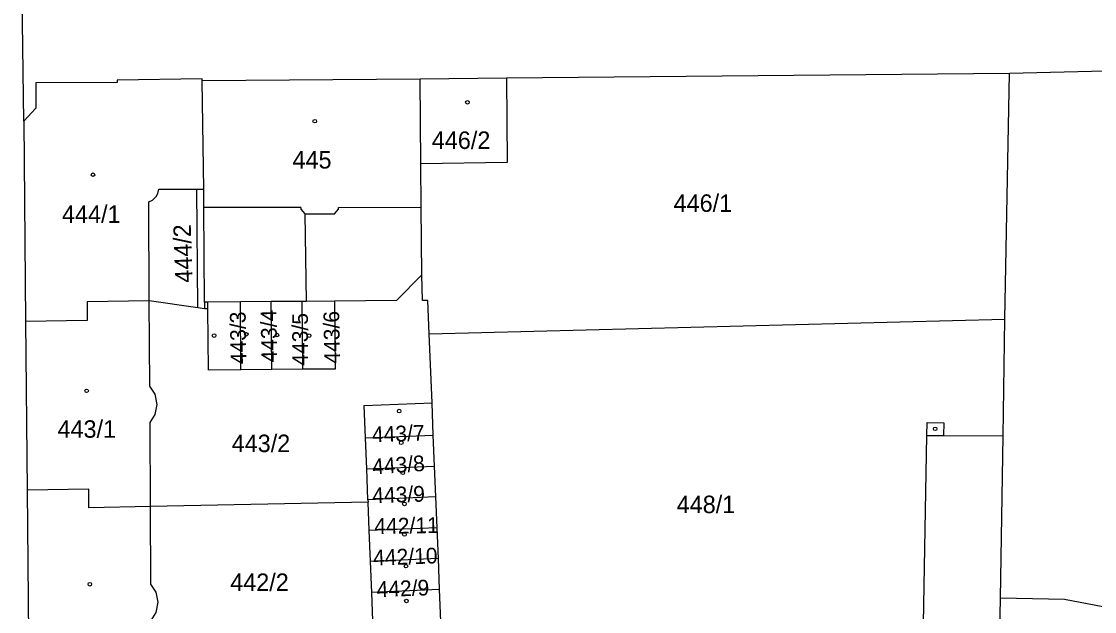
# Model space of a CAD drawing. Extents: x -733394 to -722299, y -1082822 to -1075049.
# Drawn here: x -728470.9 to -728366.6, y -1079471.2 to -1079413.8 of the extents above; entities that cross this region are included whole.
import ezdxf

# ---------------------------------------------------------------- set-up
doc = ezdxf.new("R2010")
doc.units = 0
for name, color, linetype in [('Hranice parcel', 7, 'Continuous'), ('Parcelní čísla', 7, 'Continuous'), ('Vnitřní kresba', 7, 'Continuous'), ('Značky budov', 7, 'Continuous')]:
    doc.layers.add(name, color=color, linetype=linetype)

msp = doc.modelspace()

# ---------------------------------------------------------------- linework, layer by layer
at = {"layer": 'Hranice parcel'}
for p, q in [((-728470.64, -1079423.53), (-728470.87, -1079404.92)), ((-728432.14, -1079419.44), (-728453.3, -1079419.62)), ((-728423.75, -1079419.36), (-728432.14, -1079419.44)), ((-728432.08, -1079427.67), (-728432.14, -1079419.44)), ((-728374.9, -1079418.91), (-728423.75, -1079419.36)), ((-728375.33, -1079442.75), (-728374.9, -1079418.91)), ((-728364, -1079418.64), (-728374.9, -1079418.91)), ((-728453.17, -1079430.12), (-728453.3, -1079419.62)), ((-728470.64, -1079423.53), (-728470.47, -1079442.98)), ((-728452.75, -1079441.1), (-728453.09, -1079441.1)), ((-728449.6, -1079441.07), (-728452.75, -1079441.1)), ((-728446.6, -1079441.05), (-728449.6, -1079441.07)), ((-728449.55, -1079447.67), (-728449.6, -1079441.07)), ((-728443.6, -1079441.03), (-728446.6, -1079441.05)), ((-728446.55, -1079447.65), (-728446.6, -1079441.05)), ((-728443.55, -1079447.63), (-728443.6, -1079441.03)), ((-728470.47, -1079442.98), (-728470.32, -1079459.36)), ((-728431.26, -1079444.2), (-728375.33, -1079442.75)), ((-728375.5, -1079454.1), (-728375.33, -1079442.75)), ((-728430.98, -1079450.89), (-728431.26, -1079444.2)), ((-728446.55, -1079447.65), (-728449.55, -1079447.67)), ((-728443.55, -1079447.63), (-728446.55, -1079447.65)), ((-728430.86, -1079454.03), (-728430.98, -1079450.89)), ((-728437.45, -1079454.3), (-728430.86, -1079454.03)), ((-728437.33, -1079457.3), (-728437.45, -1079454.3)), ((-728430.74, -1079457.03), (-728430.86, -1079454.03)), ((-728375.78, -1079469.87), (-728375.5, -1079454.1)), ((-728437.33, -1079457.3), (-728430.74, -1079457.03)), ((-728430.61, -1079460.03), (-728430.74, -1079457.03)), ((-728437.21, -1079460.3), (-728437.33, -1079457.3)), ((-728470.32, -1079459.36), (-728470.14, -1079480.06)), ((-728430.61, -1079460.03), (-728437.21, -1079460.3)), ((-728430.49, -1079463.03), (-728430.61, -1079460.03)), ((-728437.2, -1079460.52), (-728458.34, -1079460.95)), ((-728437.21, -1079460.3), (-728437.2, -1079460.52)), ((-728437.09, -1079463.29), (-728437.2, -1079460.52)), ((-728430.49, -1079463.03), (-728437.09, -1079463.29)), ((-728436.97, -1079466.29), (-728437.09, -1079463.29)), ((-728430.37, -1079466.02), (-728430.49, -1079463.03)), ((-728430.37, -1079466.02), (-728436.97, -1079466.29)), ((-728436.85, -1079469.29), (-728436.97, -1079466.29)), ((-728430.25, -1079469.02), (-728430.37, -1079466.02)), ((-728430.25, -1079469.02), (-728436.85, -1079469.29)), ((-728436.69, -1079472.97), (-728436.85, -1079469.29)), ((-728430.09, -1079472.87), (-728430.25, -1079469.02))]:
    msp.add_line(p, q, dxfattribs=at)
for points in [[(-728453.3, -1079419.62), (-728453.3, -1079419.43), (-728461.57, -1079419.54), (-728461.56, -1079419.76), (-728469.48, -1079419.81), (-728469.46, -1079422.28), (-728470.64, -1079423.53)], [(-728423.75, -1079419.36), (-728423.68, -1079427.56), (-728432.08, -1079427.67)], [(-728431.97, -1079438.44), (-728432.05, -1079431.89), (-728432.08, -1079427.67)], [(-728458.45, -1079440.99), (-728458.5, -1079431.37), (-728458.14, -1079431.19), (-728457.8, -1079430.86), (-728457.62, -1079430.54), (-728457.51, -1079430.15), (-728453.82, -1079430.13), (-728453.17, -1079430.12)], [(-728453.09, -1079441.1), (-728453.15, -1079431.92), (-728453.17, -1079430.12)], [(-728431.97, -1079438.44), (-728434.45, -1079440.96), (-728440.45, -1079441)], [(-728431.26, -1079444.2), (-728431.38, -1079440.94), (-728431.9, -1079440.94), (-728431.97, -1079438.44)], [(-728458.45, -1079440.99), (-728464.5, -1079441.08), (-728464.48, -1079442.89), (-728470.47, -1079442.98)], [(-728458.34, -1079460.95), (-728458.38, -1079452.81), (-728457.88, -1079452.02), (-728457.69, -1079451.04), (-728457.89, -1079450.05), (-728458.4, -1079449.27), (-728458.45, -1079440.99)], [(-728453.09, -1079441.1), (-728453.08, -1079441.75), (-728453.74, -1079441.66), (-728458.45, -1079440.99)], [(-728449.55, -1079447.67), (-728452.7, -1079447.7), (-728452.75, -1079441.75), (-728452.75, -1079441.1)], [(-728440.45, -1079441), (-728443.2, -1079441.03), (-728443.6, -1079441.03)], [(-728440.45, -1079441), (-728440.4, -1079447.6), (-728443.55, -1079447.63)], [(-728437.45, -1079454.3), (-728437.58, -1079451.15), (-728430.98, -1079450.89)], [(-728377.89, -1079535.66), (-728379.46, -1079537.61), (-728379.86, -1079537.3), (-728379.63, -1079537), (-728382.77, -1079533.71), (-728383.15, -1079533.73), (-728382.75, -1079526.18), (-728384.26, -1079526.14), (-728384.05, -1079523.07), (-728384.55, -1079523.06), (-728383.93, -1079506.08), (-728383.08, -1079506.09), (-728382.78, -1079498.3), (-728389.06, -1079498.02), (-728388.8, -1079490.97), (-728382.54, -1079491.22), (-728382.21, -1079479.61), (-728383.37, -1079479.6), (-728382.92, -1079454.06), (-728382.9, -1079452.81), (-728381.27, -1079452.84), (-728381.29, -1079454.07), (-728375.5, -1079454.1)], [(-728458.34, -1079460.95), (-728464.32, -1079461.07), (-728464.34, -1079459.28), (-728470.32, -1079459.36)], [(-728458.24, -1079479.88), (-728458.24, -1079479.17), (-728458.28, -1079472.03), (-728457.78, -1079471.24), (-728457.59, -1079470.26), (-728457.79, -1079469.27), (-728458.3, -1079468.49), (-728458.34, -1079460.95)], [(-728377.89, -1079535.66), (-728377.44, -1079523.13), (-728376.84, -1079506.33), (-728376.06, -1079484.54), (-728375.78, -1079469.87)], [(-728363.77, -1079471.1), (-728369.54, -1079469.97), (-728375.78, -1079469.87)]]:
    msp.add_lwpolyline(points, dxfattribs=at)
at = {"layer": 'Vnitřní kresba'}
for p, q in [((-728453.74, -1079441.66), (-728453.82, -1079430.13)), ((-728443.72, -1079431.91), (-728453.15, -1079431.92)), ((-728443.72, -1079431.91), (-728443.72, -1079432.08)), ((-728440.45, -1079432.53), (-728440.07, -1079432.07)), ((-728440.07, -1079431.9), (-728432.05, -1079431.89)), ((-728440.07, -1079432.07), (-728440.07, -1079431.9)), ((-728443.72, -1079432.08), (-728443.35, -1079432.53)), ((-728443.35, -1079432.53), (-728440.45, -1079432.53)), ((-728443.35, -1079432.53), (-728443.2, -1079441.03)), ((-728452.75, -1079441.75), (-728453.08, -1079441.75)), ((-728382.92, -1079454.06), (-728381.29, -1079454.07))]:
    msp.add_line(p, q, dxfattribs=at)
at = {"layer": 'Značky budov'}
for centre in [(-728427.55, -1079421.7), (-728442.38, -1079423.53), (-728463.92, -1079428.73), (-728452.16, -1079444.35), (-728449.02, -1079444.23), (-728446.05, -1079444.3), (-728442.93, -1079444.36), (-728464.54, -1079449.72), (-728434.18, -1079451.69), (-728382.11, -1079453.41), (-728433.98, -1079454.76), (-728433.83, -1079457.68), (-728433.67, -1079460.7), (-728433.67, -1079463.67), (-728433.52, -1079466.75), (-728464.23, -1079468.5), (-728433.47, -1079470.13)]:
    msp.add_circle(centre, 0.175, dxfattribs=at)

# ---------------------------------------------------------------- texts
at = {"layer": 'Parcelní čísla'}
for s, p in [('446/2', (-728431.01, -1079426.23)), ('445', (-728444.54, -1079428.13)), ('446/1', (-728407.52, -1079432.34)), ('444/1', (-728466.93, -1079433.41)), ('443/1', (-728467.37, -1079454.28)), ('443/2', (-728450.45, -1079455.67)), ('448/1', (-728407.22, -1079461.6)), ('442/2', (-728450.59, -1079469.16))]:
    msp.add_text(s, height=1.7, dxfattribs=at).set_placement(p)
for s, height, rotation, p in [('444/2', 1.7, 92, (-728454.23, -1079439.2)), ('443/3', 1.53, 91, (-728449.01, -1079447.13)), ('443/4', 1.53, 91, (-728446.02, -1079446.95)), ('443/5', 1.53, 90, (-728443.04, -1079447.28)), ('443/6', 1.53, 91, (-728439.92, -1079447.07)), ('443/7', 1.53, 2, (-728436.8, -1079454.73)), ('443/8', 1.53, 4, (-728436.75, -1079457.85)), ('443/9', 1.53, 2, (-728436.77, -1079460.65)), ('442/11', 1.53, 1, (-728436.58, -1079463.63)), ('442/10', 1.53, 2, (-728436.68, -1079466.69)), ('442/9', 1.53, 2, (-728436.35, -1079469.76))]:
    msp.add_text(s, height=height, rotation=rotation, dxfattribs=at).set_placement(p)

doc.saveas('drawing.dxf')
